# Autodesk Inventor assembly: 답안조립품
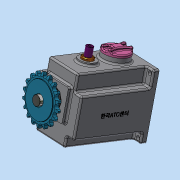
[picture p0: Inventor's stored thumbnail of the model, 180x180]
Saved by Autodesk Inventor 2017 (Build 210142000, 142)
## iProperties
Part Number: 답안조립품
Material: 일반
Document SubType Name: Assembly
Designer: MRC
Author: MRC
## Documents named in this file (16)
- C:\Users\MRC\Desktop\720212V1012\답안조립품.iam
- C:\Users\MRC\Desktop\720212V1012\본체.ipt
- C:\Users\MRC\Desktop\720212V1012\멈춤나사 M3.ipt
- C:\Users\MRC\Desktop\720212V1012\메인 축.ipt
- C:\Users\MRC\Desktop\720212V1012\베어링 608.ipt
- C:\Users\MRC\Desktop\720212V1012\베어링 6003.ipt
- C:\Users\MRC\Desktop\720212V1012\볼트 M4 x 10.ipt
- C:\Users\MRC\Desktop\720212V1012\부시.ipt
- C:\Users\MRC\Desktop\720212V1012\상부 캡.ipt
- C:\Users\MRC\Desktop\720212V1012\서브 축.ipt
- C:\Users\MRC\Desktop\720212V1012\스프로킷.ipt
- C:\Users\MRC\Desktop\720212V1012\슬라이더.ipt
- C:\Users\MRC\Desktop\720212V1012\오일 실 8 x 22 x 7.ipt
- C:\Users\MRC\Desktop\720212V1012\오일 실 17 x 32 x 8.ipt
- C:\Users\MRC\Desktop\720212V1012\커버.ipt
- C:\Users\MRC\Desktop\720212V1012\키 5 x 5.ipt
